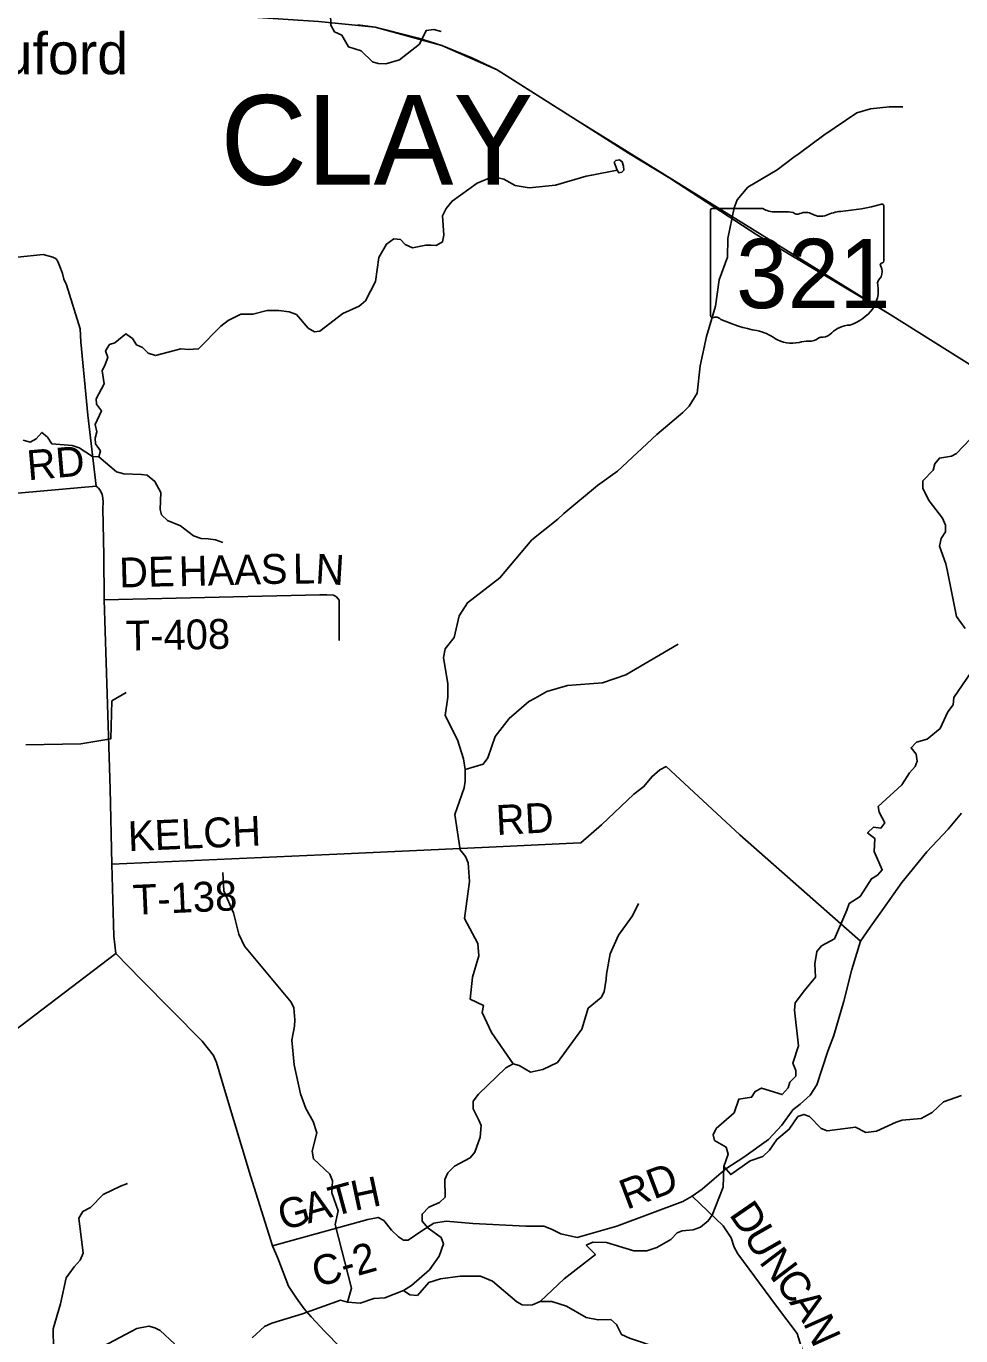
# Model space of a CAD drawing. Extents: x 0 to 34, y 0 to 22.
# Drawn here: x 3.822 to 5.601, y 15.554 to 18.045 of the extents above; entities that cross this region are included whole.
import ezdxf

# ---------------------------------------------------------------- set-up
doc = ezdxf.new("R2010")
doc.units = 0
for name, color, linetype in [('Default', 7, 'Continuous'), ('GM_X_County_Road', 7, 'Continuous'), ('GM_X_County_Road_Text', 7, 'Continuous'), ('GM_X_Minor_Lake', 7, 'Continuous'), ('GM_X_Minor_River', 7, 'Continuous'), ('GM_X_State_Location', 7, 'Continuous'), ('GM_X_State_Route', 7, 'Continuous'), ('GM_X_State_Shield', 7, 'Continuous'), ('GM_X_Township_Road', 7, 'Continuous'), ('GM_X_Township_Road_Text', 7, 'Continuous'), ('GM_X_Township_Text', 7, 'Continuous'), ('GM_X_Unincorporated_Text', 7, 'Continuous')]:
    doc.layers.add(name, color=color, linetype=linetype)

msp = doc.modelspace()

# ---------------------------------------------------------------- linework, layer by layer
at = {"layer": 'Default'}
msp.add_lwpolyline([(8.161, 15.8436), (7.9019, 15.9854), (7.7478, 16.0791), (7.6481, 16.1403), (7.4293, 16.2693), (7.2434, 16.3742), (6.998, 16.5438), (6.6485, 16.765), (6.4043, 16.9203), (6.0579, 17.1312), (5.7891, 17.2948), (5.4666, 17.4969), (4.8712, 17.8663), (4.7185, 17.9622), (4.6135, 18.0087), (4.4868, 18.0434), (4.3784, 18.0545), (4.2056, 18.0659), (3.9354, 18.0836), (3.6991, 18.1432)], dxfattribs=at)
at = {"layer": 'GM_X_County_Road'}
msp.add_lwpolyline([(4.2913, 15.7251), (4.4725, 15.775), (4.492, 15.7792), (4.5032, 15.7733), (4.5177, 15.7548), (4.5312, 15.742), (4.5402, 15.7358), (4.5496, 15.736), (4.5754, 15.754), (4.598, 15.7684), (4.6219, 15.7721), (4.6723, 15.7677), (4.7735, 15.7627), (4.8076, 15.7624), (4.8219, 15.7568), (4.8396, 15.7477), (4.871, 15.7407), (4.9464, 15.7623), (5.0718, 15.8095), (5.0896, 15.8198), (5.1089, 15.833), (5.1315, 15.8523), (5.1538, 15.8716), (5.188, 15.8941), (5.2352, 15.9273), (5.2603, 15.9549), (5.2813, 15.9837), (5.2951, 15.9948), (5.314, 16.0115), (5.3268, 16.0317), (5.3477, 16.0958), (5.3592, 16.1252), (5.3785, 16.1908), (5.3936, 16.2508), (5.4098, 16.305), (5.4287, 16.3313), (5.4536, 16.3669), (5.489, 16.4163), (5.5366, 16.4745), (5.5768, 16.5178), (5.6024, 16.5484)], dxfattribs=at)
at = {"layer": 'GM_X_Minor_Lake'}
for points in [[(4.947, 17.7717), (4.9503, 17.7663), (4.956, 17.7677), (4.9599, 17.7718), (4.9589, 17.779), (4.9564, 17.7874), (4.9515, 17.7913), (4.9443, 17.7899), (4.9412, 17.7869)], [(4.9412, 17.7869), (4.947, 17.7717)]]:
    msp.add_lwpolyline(points, dxfattribs=at)
at = {"layer": 'GM_X_Minor_River'}
for points in [[(4.4018, 18.0701), (4.402, 18.0475), (4.409, 18.0345), (4.423, 18.0286), (4.4359, 18.006), (4.4596, 17.9988), (4.4817, 17.9775), (4.4922, 17.9747), (4.507, 17.9741), (4.5326, 17.9816), (4.5706, 18.0109), (4.5835, 18.0372), (4.598, 18.0392), (4.612, 18.0356)], [(4.7488, 16.0716), (4.7078, 16.131), (4.6902, 16.1692), (4.6926, 16.1824), (4.6674, 16.1942), (4.6717, 16.2362), (4.684, 16.2769), (4.682, 16.3004), (4.6565, 16.3478), (4.6658, 16.4182), (4.6632, 16.4535), (4.6581, 16.466), (4.6484, 16.4787), (4.6379, 16.5459), (4.656, 16.5964), (4.6577, 16.6089), (4.658, 16.6312), (4.6548, 16.6514), (4.6432, 16.6879), (4.6195, 16.7341), (4.6245, 16.7689), (4.6248, 16.7946), (4.6164, 16.8444), (4.62, 16.8606), (4.637, 16.8823), (4.6463, 16.9239), (4.6625, 16.9486), (4.7238, 16.9959), (4.7847, 17.0684), (4.8342, 17.1075), (4.8453, 17.1183), (4.9097, 17.1716), (4.9477, 17.199), (5.0226, 17.2688), (5.0717, 17.3105), (5.0843, 17.3225), (5.0991, 17.3473), (5.1051, 17.3991), (5.1172, 17.455), (5.1339, 17.5127), (5.1414, 17.5627), (5.1568, 17.606), (5.1577, 17.6416), (5.1698, 17.6998), (5.1757, 17.7153), (5.1958, 17.7389), (5.2516, 17.7722), (5.2831, 17.796), (5.2934, 17.803), (5.3402, 17.8384), (5.4033, 17.8803), (5.4292, 17.8883), (5.4646, 17.8919), (5.4908, 17.892)], [(3.9605, 17.2261), (3.9637, 17.2374), (3.9541, 17.2508), (3.9535, 17.2614), (3.9571, 17.2734), (3.9539, 17.2879), (3.9657, 17.3134), (3.956, 17.3265), (3.9554, 17.3363), (3.9711, 17.3652), (3.9669, 17.3895), (3.9728, 17.4015), (3.9775, 17.4151), (3.9736, 17.428), (3.981, 17.44), (3.9909, 17.4428), (4.012, 17.4599), (4.0248, 17.451), (4.0322, 17.4391), (4.0438, 17.4343), (4.0543, 17.4232), (4.0682, 17.4188), (4.117, 17.4316), (4.131, 17.4302), (4.1504, 17.4314), (4.1928, 17.4749), (4.2066, 17.4857), (4.2307, 17.4977), (4.2538, 17.4973), (4.2812, 17.5044), (4.2937, 17.5046), (4.3032, 17.5044), (4.3229, 17.5022), (4.3365, 17.497), (4.3592, 17.4709), (4.3712, 17.4639), (4.3811, 17.4652), (4.4249, 17.4989), (4.4558, 17.5128), (4.4681, 17.5231), (4.4869, 17.5599), (4.4933, 17.6053), (4.5082, 17.6308), (4.522, 17.6408), (4.5345, 17.6398), (4.5438, 17.6302), (4.5574, 17.6235), (4.5828, 17.6287), (4.5931, 17.6289), (4.6029, 17.628), (4.6148, 17.635), (4.6173, 17.6478), (4.6145, 17.6846), (4.6215, 17.6985), (4.6328, 17.7127), (4.6804, 17.7468), (4.7033, 17.7566), (4.7151, 17.7579), (4.7313, 17.7546), (4.7531, 17.7425), (4.7796, 17.7382), (4.8297, 17.743), (4.888, 17.7598), (4.8987, 17.7623), (4.947, 17.7717)], [(5.6723, 17.3158), (5.593, 17.2324), (5.5835, 17.2276), (5.5603, 17.2238), (5.5514, 17.2129), (5.5482, 17.2009), (5.5286, 17.1803), (5.5284, 17.1659), (5.541, 17.1426), (5.5659, 17.1096), (5.5718, 17.0963), (5.5716, 17.0834), (5.5639, 17.0706), (5.5607, 17.0563), (5.5723, 17.0224), (5.5748, 17.0113), (5.5926, 16.9224), (5.609, 16.8998)], [(3.8165, 17.2577), (3.8301, 17.2541), (3.8416, 17.2607), (3.8524, 17.2726), (3.8629, 17.2637), (3.8714, 17.2507), (3.9096, 17.2478), (3.9232, 17.243), (3.9484, 17.227), (3.9605, 17.2261), (3.9945, 17.1974), (4.0081, 17.1938), (4.0418, 17.1928), (4.0528, 17.1911), (4.0674, 17.1795), (4.0788, 17.1581), (4.0776, 17.1259), (4.0797, 17.1161), (4.0916, 17.1049), (4.1161, 17.095), (4.1408, 17.0756), (4.1552, 17.0708), (4.1688, 17.0702), (4.1828, 17.068), (4.1963, 17.0629)], [(4.658, 16.6312), (4.6919, 16.6413), (4.7007, 16.6537), (4.7146, 16.694), (4.7415, 16.7281), (4.7788, 16.7605), (4.791, 16.7672), (4.8135, 16.7797), (4.8527, 16.7912), (4.9192, 16.7959), (4.9634, 16.8116), (5.0631, 16.8696)], [(5.6204, 16.8166), (5.5878, 16.7681), (5.5865, 16.7541), (5.5761, 16.741), (5.5616, 16.7094), (5.5371, 16.6889), (5.5169, 16.6835), (5.5065, 16.6727), (5.5158, 16.6604), (5.5179, 16.6471), (5.5144, 16.6373), (5.5032, 16.6253), (5.4889, 16.6024), (5.4439, 16.561), (5.4453, 16.55), (5.4564, 16.5298), (5.4491, 16.52), (5.4351, 16.5214), (5.4235, 16.5109), (5.4371, 16.5001), (5.436, 16.4755), (5.4514, 16.4407), (5.4426, 16.4306), (5.4311, 16.4236), (5.4094, 16.3898), (5.3887, 16.3761), (5.384, 16.3637), (5.3609, 16.3094), (5.3361, 16.2958), (5.3272, 16.2853), (5.3231, 16.2618), (5.3246, 16.2364), (5.3034, 16.2109), (5.2857, 16.1877), (5.2847, 16.1737), (5.2918, 16.1057), (5.2811, 16.0725), (5.2869, 16.0584), (5.2872, 16.0481), (5.2756, 16.0362), (5.2725, 16.026), (5.2613, 16.0129), (5.2217, 16.0253), (5.2094, 16.019), (5.2028, 16.0077), (5.1785, 16.0043), (5.1695, 15.9783), (5.1357, 15.9481), (5.1298, 15.9361), (5.1324, 15.9258)], [(3.8216, 16.678), (3.9263, 16.6803), (3.9837, 16.6899), (3.9853, 16.7618), (4.0124, 16.7776)], [(4.434, 15.6181), (4.4416, 15.6446), (4.4106, 15.766), (4.4159, 15.792), (4.4042, 15.826), (4.4053, 15.8487), (4.4001, 15.8617), (4.369, 15.8906), (4.3666, 15.905), (4.3754, 15.9401), (4.3685, 15.9618), (4.3548, 15.9863), (4.3442, 16.0145), (4.3324, 16.0693), (4.3281, 16.1163), (4.333, 16.1432), (4.3335, 16.1549), (4.3315, 16.1777), (4.3267, 16.1884), (4.2379, 16.2954), (4.2272, 16.3183), (4.2171, 16.3586), (4.1983, 16.4006), (4.1965, 16.4355)], [(4.5405, 15.64), (4.5558, 15.6496), (4.5896, 15.6798), (4.6085, 15.7053), (4.6168, 15.7287), (4.612, 15.7409), (4.5872, 15.7587), (4.576, 15.7722), (4.5758, 15.7854), (4.5889, 15.7985), (4.6087, 15.8073), (4.6195, 15.8177), (4.6192, 15.8515), (4.625, 15.8643), (4.6373, 15.8766), (4.6675, 15.8928), (4.6764, 15.9033), (4.6866, 15.9316), (4.688, 15.9543), (4.684, 15.9642), (4.6729, 15.986), (4.6731, 16.0004), (4.6831, 16.0139), (4.735, 16.0639), (4.7488, 16.0716), (4.7608, 16.068), (4.7819, 16.0556), (4.8055, 16.0609), (4.8333, 16.0741), (4.8797, 16.1371), (4.892, 16.1771), (4.9165, 16.1979), (4.9223, 16.2085), (4.9261, 16.2323), (4.927, 16.2421), (4.9339, 16.2807), (4.9496, 16.3161), (4.9759, 16.3532), (4.9875, 16.3761)], [(5.1502, 15.8758), (5.1633, 15.8608), (5.2001, 15.8868), (5.2244, 15.8952), (5.2371, 15.9071), (5.2507, 15.9277), (5.2744, 15.9471), (5.2911, 15.9715), (5.3025, 15.9751), (5.3131, 15.9715), (5.3355, 15.9484), (5.3468, 15.9441), (5.4003, 15.9512), (5.4203, 15.9407), (5.4408, 15.9434), (5.4782, 15.9606), (5.4896, 15.9642), (5.5257, 15.9671), (5.5467, 15.9789), (5.5682, 15.9991), (5.6021, 16.0114)], [(5.1324, 15.9258), (5.1545, 15.9126), (5.1585, 15.8996), (5.1502, 15.8758), (5.1486, 15.8368), (5.1278, 15.7837), (5.1204, 15.7724), (5.1055, 15.7609), (5.0914, 15.7554), (5.0705, 15.7538), (5.061, 15.7502), (5.049, 15.7375), (5.0227, 15.722), (5.0033, 15.7155), (4.979, 15.7158), (4.9269, 15.7315), (4.9008, 15.7319), (4.8882, 15.7264), (4.9057, 15.7087), (4.8464, 15.6626), (4.8003, 15.6193), (4.7862, 15.6127), (4.7767, 15.6121), (4.7665, 15.613), (4.7559, 15.6189), (4.7098, 15.6582), (4.6868, 15.6673), (4.6481, 15.6672), (4.6109, 15.6624), (4.5885, 15.6556), (4.5669, 15.6305), (4.5525, 15.6319), (4.5405, 15.64), (4.505, 15.6261), (4.4838, 15.625), (4.4579, 15.6159), (4.434, 15.6181), (4.4208, 15.6221), (4.348, 15.5956), (4.2898, 15.5782), (4.276, 15.5716), (4.2526, 15.55)], [(3.8652, 15.5114), (3.8742, 15.5291), (3.8735, 15.5674), (3.8875, 15.6149), (3.8984, 15.6641), (3.9138, 15.6855), (3.9254, 15.6982), (3.9309, 15.7114), (3.9227, 15.7778), (3.9304, 15.7906), (3.9449, 15.798), (3.9692, 15.8226), (4.0016, 15.8385), (4.015, 15.8436)], [(4.8003, 15.6193), (4.8225, 15.6195), (4.8504, 15.6103), (4.8879, 15.5891), (4.9106, 15.5841), (4.9352, 15.5852), (4.9457, 15.5755), (4.9552, 15.5563), (4.9702, 15.5492), (5.029, 15.5299), (5.0521, 15.5071), (5.0652, 15.4993), (5.0759, 15.5017), (5.105, 15.5201), (5.1182, 15.518), (5.1283, 15.511), (5.1396, 15.5088), (5.1539, 15.5017), (5.2313, 15.4631), (5.2566, 15.4581), (5.2683, 15.4586)], [(4.1049, 15.5389), (4.0772, 15.564), (4.0674, 15.5691), (4.0561, 15.5723), (4.0329, 15.5681), (3.924, 15.5105)]]:
    msp.add_lwpolyline(points, dxfattribs=at)
at = {"layer": 'GM_X_State_Route'}
for points in [[(4.4538, 18.0482), (4.4868, 18.0434), (4.5096, 18.0381), (4.5691, 18.0228), (4.6135, 18.0087), (4.6702, 17.9855), (4.7185, 17.9622), (4.7704, 17.9294), (4.8712, 17.8663), (4.9685, 17.8039), (5.0472, 17.7563), (5.2128, 17.6483), (5.4666, 17.4969), (5.7891, 17.2948), (5.8999, 17.2273), (6.0579, 17.1312), (6.4043, 16.9203)], [(4.4202, 15.5326), (4.3908, 15.5621), (4.365, 15.5901), (4.3514, 15.6053), (4.3368, 15.6255), (4.3215, 15.6487), (4.3112, 15.6752), (4.3013, 15.702), (4.2913, 15.7251), (4.249, 15.8583), (4.2014, 16.016), (4.1844, 16.0741), (4.1787, 16.0875), (4.1574, 16.1147), (4.0415, 16.2318), (3.9927, 16.2813), (3.9891, 16.3144), (3.9855, 16.4514), (3.9822, 16.5948), (3.9767, 16.7753), (3.9709, 16.954), (3.9701, 17.0385), (3.9683, 17.1276), (3.9686, 17.1405), (3.9684, 17.1477), (3.9671, 17.1545), (3.9642, 17.1599), (3.9624, 17.1634), (3.9601, 17.1663), (3.9587, 17.1679), (3.9554, 17.1704), (3.94, 17.3053), (3.9262, 17.4448), (3.925, 17.4694), (3.8992, 17.5535), (3.8938, 17.5643), (3.8914, 17.5749), (3.8879, 17.5853), (3.8825, 17.5975), (3.8792, 17.6029), (3.8732, 17.6058), (3.8548, 17.6108), (3.8061, 17.6061)]]:
    msp.add_lwpolyline(points, dxfattribs=at)
at = {"layer": 'GM_X_State_Shield'}
for p, q in [((5.1247, 17.695), (5.1247, 17.4949)), ((5.2245, 17.6985), (5.128, 17.6985)), ((5.4543, 17.5987), (5.4543, 17.7034)), ((5.4543, 17.5988), (5.4543, 17.5987))]:
    msp.add_line(p, q, dxfattribs=at)
for centre, major_axis, start_param, end_param in [((5.1285, 17.6955), (0.00382, 0), 1.712693, 3.28349), ((5.2475, 17.7217), (0.037, 0), 4.042523, 4.731795), ((5.2597, 17.5861), (0.133, 0), 1.404758, 1.657858), ((5.2899, 17.6965), (0.0107, 0), 3.836095, 5.185415), ((5.3056, 17.6734), (0.0222, 0), 0.950623, 2.079405), ((5.3815, 17.6373), (0.0703, 0), 1.699011, 2.107814), ((5.3369, 17.9713), (0.3495, 0), 4.814394, 5.042369), ((5.4506, 17.7039), (0.00367, 0), 6.141152, 7.989035), ((5.3343, 17.7051), (0.0267, 0), 4.081561, 5.145723), ((5.4534, 17.5911), (0.00568, 0), 1.883978, 3.671073), ((5.4504, 17.5983), (0.00393, 0), 5.05454, 6.418171), ((5.4674, 17.5549), (0.0248, 0), 2.387724, 3.262537), ((5.4173, 17.5778), (0.0341, 0), 5.934695, 6.695948), ((5.3565, 17.5416), (0.0874, 0), 5.101752, 6.440018), ((5.1285, 17.4945), (0.00385, 0), 3.00124, 4.508301), ((5.1291, 17.5149), (0.0294, 0), 4.665946, 4.897461), ((5.1351, 17.4834), (0.0106, 0), 0.519207, 1.627899), ((5.2689, 17.6632), (0.2524, 0), 4.195997, 4.488961), ((5.1937, 17.405), (0.079, 0), 0.823519, 1.323587), ((5.3933, 17.4387), (0.0479, 0), 1.647645, 2.488434), ((5.2791, 17.4824), (0.0501, 0), 4.026481, 4.996735), ((5.3081, 17.4132), (0.0412, 0), 1.495662, 1.94098), ((5.3117, 17.4674), (0.0267, 0), 4.691044, 5.507374), ((5.3359, 17.448), (0.00752, 0), 1.147584, 2.315152), ((5.3327, 17.4755), (0.0282, 0), 4.937069, 5.64225)]:
    msp.add_ellipse(centre, major_axis=major_axis, ratio=0.8, start_param=start_param, end_param=end_param, dxfattribs=at)
at = {"layer": 'GM_X_Township_Road'}
for points in [[(3.321, 17.3562), (3.3276, 17.3451), (3.3311, 17.1583), (3.332, 17.1424), (3.3318, 17.1307), (3.3317, 17.1246), (3.3328, 17.1204), (3.3392, 17.118), (3.3689, 17.1198), (3.6423, 17.1426), (3.9554, 17.1704)], [(3.9709, 16.954), (4.3811, 16.9637), (4.3947, 16.9634), (4.4069, 16.9632), (4.4129, 16.96), (4.4177, 16.9535), (4.418, 16.9459), (4.418, 16.8766)], [(4.8634, 16.4909), (4.8782, 16.4916), (4.9171, 16.5261), (4.9788, 16.5845), (4.998, 16.5989), (5.0128, 16.6176), (5.0282, 16.631), (5.04, 16.6368), (5.1806, 16.5068), (5.4098, 16.305)], [(3.9855, 16.4514), (4.4136, 16.4702), (4.7034, 16.4838), (4.8634, 16.4909)], [(3.1188, 15.6106), (3.3713, 15.8058), (3.7002, 16.0586), (3.9927, 16.2813)], [(5.4349, 15.1105), (5.4207, 15.1503), (5.3997, 15.2091), (5.3489, 15.3639), (5.3191, 15.462), (5.2897, 15.5586), (5.2503, 15.6106), (5.1765, 15.71), (5.1695, 15.7226), (5.1638, 15.7406), (5.149, 15.7629), (5.0896, 15.8198)]]:
    msp.add_lwpolyline(points, dxfattribs=at)

# ---------------------------------------------------------------- texts
at = {"layer": 'GM_X_County_Road_Text'}
for s, height, rotation, p in [('RD', 0.05682, 20.7867, (4.9652, 15.7935)), ('T', 0.0568, 15.181, (4.407, 15.7805)), ('H', 0.0568, 11.9956, (4.4472, 15.7914)), ('A', 0.0568, 15.2578, (4.3588, 15.7673)), ('G', 0.0568, 15.2534, (4.3106, 15.7542)), ('C-2', 0.05682, 15.6951, (4.3756, 15.6459))]:
    msp.add_text(s, height=height, rotation=rotation, dxfattribs=at).set_placement(p)
at = {"layer": 'GM_X_State_Location'}
msp.add_text('321', height=0.000189, rotation=0, dxfattribs=at).set_placement((5.2189, 17.5679))
for s in ['s', 'r']:
    msp.add_text(s, height=0.000189, dxfattribs=at).set_placement((5.2858, 17.5817))
at = {"layer": 'GM_X_State_Shield'}
msp.add_text('321', height=0.13184, dxfattribs=at).set_placement((5.1733, 17.509))
at = {"layer": 'GM_X_Township_Road_Text'}
for s, height, rotation, p in [('RD', 0.05682, 4.9281, (3.8262, 17.1815)), ('HAAS', 0.05682, 1.4503, (4.1134, 16.9799)), ('L', 0.0568, 0.51, (4.3301, 16.9849)), ('N', 0.0568, 356.6139, (4.3716, 16.9853)), ('DE', 0.05682, 1.5473, (4, 16.9774)), ('T-408', 0.05682, 1.1238, (4.0125, 16.8573)), ('RD', 0.05682, 2.9612, (4.7178, 16.5066)), ('KELCH', 0.05682, 2.4719, (4.0171, 16.4758)), ('T-138', 0.05682, 2.5258, (4.0266, 16.3549)), ('D', 0.0568, 304.5095, (5.1588, 15.7847)), ('U', 0.0568, 299.6782, (5.1865, 15.7446)), ('N', 0.0568, 307.1501, (5.2157, 15.6944)), ('C', 0.0568, 306.7614, (5.2458, 15.6546)), ('A', 0.0568, 304.2746, (5.2734, 15.6178)), ('N', 0.0568, 294.1452, (5.3003, 15.5788))]:
    msp.add_text(s, height=height, rotation=rotation, dxfattribs=at).set_placement(p)
at = {"layer": 'GM_X_Township_Text'}
msp.add_text('CLAY', height=0.17045, rotation=0, dxfattribs=at).set_placement((4.1921, 17.7438))
at = {"layer": 'GM_X_Unincorporated_Text'}
msp.add_text('Buford', height=0.07898, rotation=0, dxfattribs=at).set_placement((3.7053, 17.954))

doc.saveas('drawing.dxf')
